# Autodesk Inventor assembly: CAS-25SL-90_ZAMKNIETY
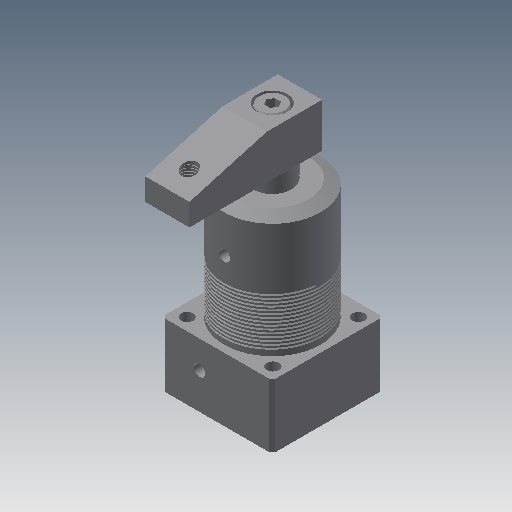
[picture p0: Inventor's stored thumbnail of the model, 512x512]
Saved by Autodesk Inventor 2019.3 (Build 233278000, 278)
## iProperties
Created: 2010-02
Part Number: CAS-25SL-90_ZAMKNIETY
Material: Ogólny
Document SubType Name: Assembly
Designer: CADENGINEERING4
Sending System: PRO/ENGINEER BY PARAMETRIC TECHNOLOGY CORPORATION, 2007170
Preprocessor: PRO/ENGINEER BY PARAMETRIC TECHNOLOGY CORPORATION, 2007170
Title: CAS-25S_ASM
Author: Administrator
Revision Number: 2LAST_VERSION
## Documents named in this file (8)
- D:\Vault_2016\Projekty\STRONA\Pneumatic\Line ; Pipe connecct - type\cas-25s_asm\CAS-25SL-90_ZAMKNIETY.iam
- D:\Vault_2016\Projekty\STRONA\Pneumatic\Line ; Pipe connecct - type\cas-25s_asm\CAS-25BT.ipt
- D:\Vault_2016\Projekty\STRONA\Pneumatic\Line ; Pipe connecct - type\cas-25s_asm\CAS-25SHSG.ipt
- D:\Vault_2016\Projekty\STRONA\Pneumatic\Line ; Pipe connecct - type\cas-25s_asm\CAS-25HG.ipt
- D:\Vault_2016\Projekty\STRONA\Pneumatic\Line ; Pipe connecct - type\cas-25s_asm\PRT0001M3.ipt
- D:\Vault_2016\Projekty\STRONA\Pneumatic\Line ; Pipe connecct - type\cas-25s_asm\CAS-25SYABI.ipt
- D:\Vault_2016\Projekty\STRONA\Pneumatic\Line ; Pipe connecct - type\cas-25s_asm\M6LC.ipt
- D:\Vault_2016\Projekty\STRONA\Pneumatic\Line ; Pipe connecct - type\cas-25s_asm\PRT0001.ipt
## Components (10 placed, 10 different names)
1. CAS-25BT_10 — Zestawiające:5, Kątowe:1, Równoległe:1
2. CAS-25SHSG_11 — Zestawiające:1, Zestawiające:2, Zestawiające:4, Zestawiające:5
3. CAS-25HG_12
4. PRT0001M3_13
5. PRT0001M3_14
6. PRT0001M3_15
7. PRT0001M3_16
8. CAS-25SYABI_17 — Zestawiające:1, Zestawiające:3, Zestawiające:4, Kątowe:1, Równoległe:1
9. M6LC_18 — Zestawiające:2, Zestawiające:3
10. PRT0001_19
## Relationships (7: Mate 5, Angle 1, Flush 1)
- Zestawiające:1 [Mate]: CAS-25SHSG_11 ↔ CAS-25SYABI_17
- Zestawiające:2 [Mate]: CAS-25SHSG_11 ↔ M6LC_18
- Zestawiające:3 [Mate]: CAS-25SYABI_17 ↔ M6LC_18
- Zestawiające:4 [Mate]: CAS-25SHSG_11 ↔ CAS-25SYABI_17
- Zestawiające:5 [Mate]: CAS-25BT_10 ↔ CAS-25SHSG_11
- Kątowe:1 [Angle]: CAS-25BT_10 ↔ CAS-25SYABI_17
- Równoległe:1 [Flush]: CAS-25BT_10 ↔ CAS-25SYABI_17
